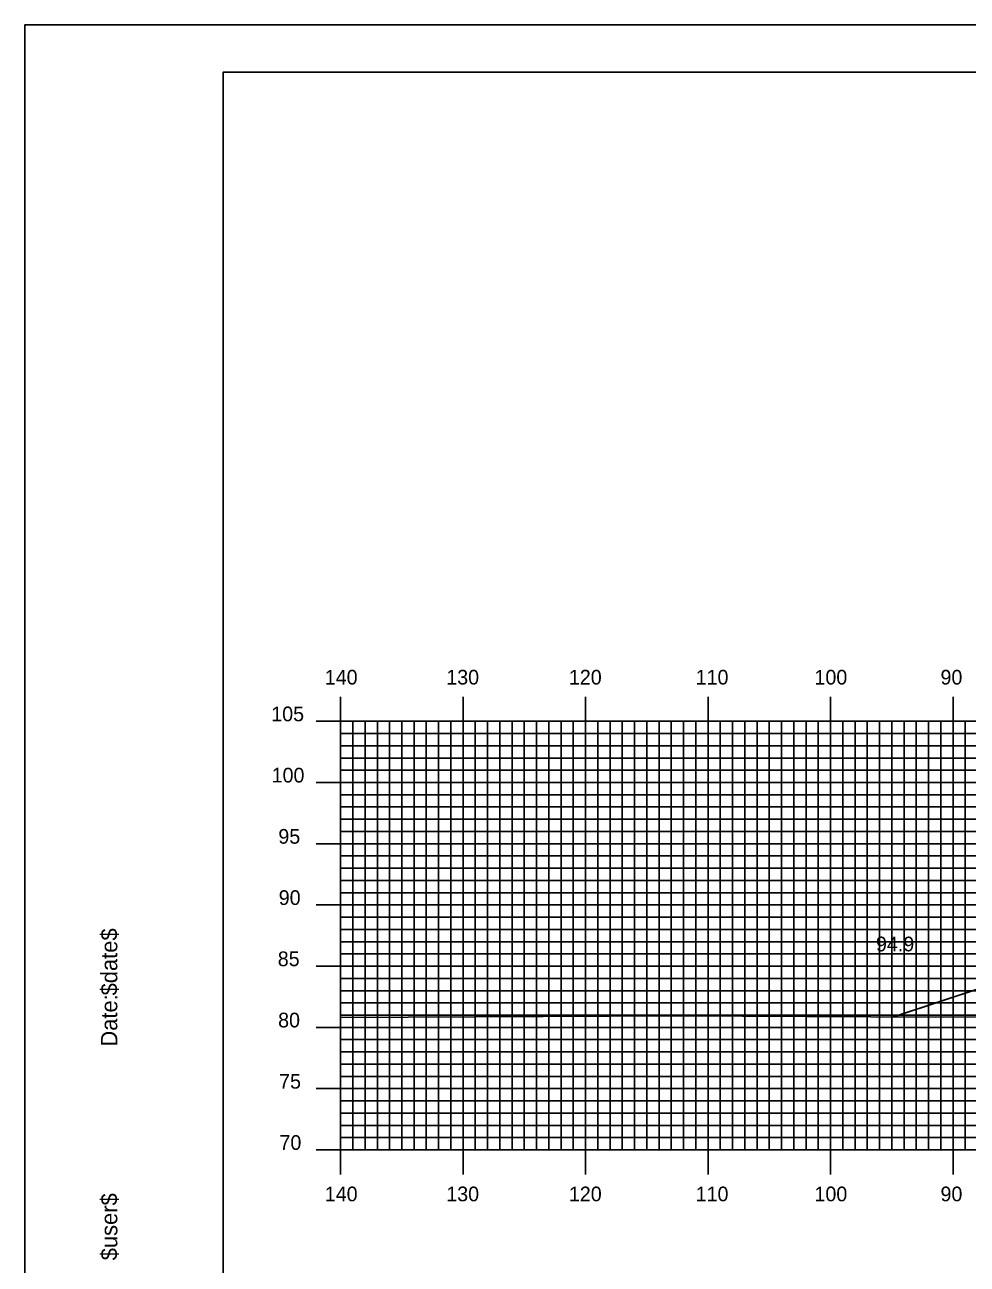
# Model space of a CAD drawing. Extents: x 1756675 to 1757019, y 442591 to 442811.
# Drawn here: x 1756675.3 to 1756752.2, y 442709.3 to 442810.5 of the extents above; entities that cross this region are included whole.
import ezdxf

# ---------------------------------------------------------------- set-up
doc = ezdxf.new("R2010")
doc.units = 0
for name, color, linetype in [('BORDER', 7, 'Continuous'), ('D_Roadway_Centerline', 7, 'Continuous'), ('D_Roadway_SlopeLines', 7, 'Continuous'), ('D_Text_Standard', 7, 'Continuous'), ('H_V ANNOTATION', 7, 'Continuous'), ('MAJOR', 7, 'Continuous'), ('MINOR', 7, 'Continuous'), ('PLOT BOUNDARY', 7, 'Continuous'), ('S_Roadway_Centerline', 7, 'Continuous')]:
    doc.layers.add(name, color=color, linetype=linetype)

msp = doc.modelspace()

# ---------------------------------------------------------------- linework, layer by layer
at = {"layer": 'BORDER'}
msp.add_lwpolyline([(1756691.48, 442596.67), (1757011.48, 442596.67), (1757011.48, 442806.67), (1756691.48, 442806.67)], close=True, dxfattribs=at)
at = {"layer": 'D_Roadway_Centerline'}
msp.add_lwpolyline([(1756746.21, 442729.53), (1756746.45, 442729.6), (1756746.5, 442729.61), (1756784.93, 442742.34), (1756786.99, 442742.43), (1756787.74, 442742.47), (1756787.94, 442742.47), (1756792.2, 442742.67), (1756795.97, 442742.83), (1756797.16, 442742.89), (1756798.1, 442742.93), (1756798.44, 442742.94), (1756798.51, 442742.95), (1756803.7, 442743.18), (1756810.03, 442743.46), (1756829.08, 442743.84), (1756841.08, 442744.08), (1756853.08, 442743.84), (1756862.37, 442743.47), (1756867.31, 442742.24)], dxfattribs=at)
at = {"layer": 'D_Roadway_SlopeLines'}
msp.add_lwpolyline([(1756784.93, 442742.34), (1756746.21, 442729.53)], dxfattribs=at)
at = {"layer": 'MAJOR'}
for p, q in [((1756701.08, 442755.67), (1756701.08, 442753.67)), ((1756711.08, 442755.67), (1756711.08, 442753.67)), ((1756721.08, 442755.67), (1756721.08, 442753.67)), ((1756731.08, 442755.67), (1756731.08, 442753.67)), ((1756741.08, 442755.67), (1756741.08, 442753.67)), ((1756751.08, 442755.67), (1756751.08, 442753.67)), ((1756699.08, 442753.67), (1756701.08, 442753.67)), ((1756701.08, 442753.67), (1756981.08, 442753.67)), ((1756701.08, 442718.67), (1756701.08, 442753.67)), ((1756701.08, 442718.67), (1756701.08, 442753.67)), ((1756701.08, 442753.67), (1756981.08, 442753.67)), ((1756711.08, 442718.67), (1756711.08, 442753.67)), ((1756721.08, 442718.67), (1756721.08, 442753.67)), ((1756731.08, 442718.67), (1756731.08, 442753.67)), ((1756741.08, 442718.67), (1756741.08, 442753.67)), ((1756751.08, 442718.67), (1756751.08, 442753.67)), ((1756699.08, 442748.67), (1756701.08, 442748.67)), ((1756701.08, 442748.67), (1756981.08, 442748.67)), ((1756699.08, 442743.67), (1756701.08, 442743.67)), ((1756701.08, 442743.67), (1756981.08, 442743.67)), ((1756699.08, 442738.67), (1756701.08, 442738.67)), ((1756701.08, 442738.67), (1756981.08, 442738.67)), ((1756699.08, 442733.67), (1756701.08, 442733.67)), ((1756701.08, 442733.67), (1756981.08, 442733.67)), ((1756699.08, 442728.67), (1756701.08, 442728.67)), ((1756701.08, 442728.67), (1756981.08, 442728.67)), ((1756699.08, 442723.67), (1756701.08, 442723.67)), ((1756701.08, 442723.67), (1756981.08, 442723.67)), ((1756699.08, 442718.67), (1756701.08, 442718.67)), ((1756701.08, 442718.67), (1756981.08, 442718.67)), ((1756701.08, 442718.67), (1756981.08, 442718.67)), ((1756701.08, 442716.66), (1756701.08, 442718.67)), ((1756711.08, 442716.66), (1756711.08, 442718.67)), ((1756721.08, 442716.66), (1756721.08, 442718.67)), ((1756731.08, 442716.66), (1756731.08, 442718.67)), ((1756741.08, 442716.66), (1756741.08, 442718.67)), ((1756751.08, 442716.66), (1756751.08, 442718.67))]:
    msp.add_line(p, q, dxfattribs=at)
at = {"layer": 'MINOR'}
for p, q in [((1756702.08, 442718.67), (1756702.08, 442753.67)), ((1756703.08, 442718.67), (1756703.08, 442753.67)), ((1756704.08, 442718.67), (1756704.08, 442753.67)), ((1756705.08, 442718.67), (1756705.08, 442753.67)), ((1756706.08, 442718.67), (1756706.08, 442753.67)), ((1756707.08, 442718.67), (1756707.08, 442753.67)), ((1756708.08, 442718.67), (1756708.08, 442753.67)), ((1756709.08, 442718.67), (1756709.08, 442753.67)), ((1756710.08, 442718.67), (1756710.08, 442753.67)), ((1756712.08, 442718.67), (1756712.08, 442753.67)), ((1756713.08, 442718.67), (1756713.08, 442753.67)), ((1756714.08, 442718.67), (1756714.08, 442753.67)), ((1756715.08, 442718.67), (1756715.08, 442753.67)), ((1756716.08, 442718.67), (1756716.08, 442753.67)), ((1756717.08, 442718.67), (1756717.08, 442753.67)), ((1756718.08, 442718.67), (1756718.08, 442753.67)), ((1756719.08, 442718.67), (1756719.08, 442753.67)), ((1756720.08, 442718.67), (1756720.08, 442753.67)), ((1756722.08, 442718.67), (1756722.08, 442753.67)), ((1756723.08, 442718.67), (1756723.08, 442753.67)), ((1756724.08, 442718.67), (1756724.08, 442753.67)), ((1756725.08, 442718.67), (1756725.08, 442753.67)), ((1756726.08, 442718.67), (1756726.08, 442753.67)), ((1756727.08, 442718.67), (1756727.08, 442753.67)), ((1756728.08, 442718.67), (1756728.08, 442753.67)), ((1756729.08, 442718.67), (1756729.08, 442753.67)), ((1756730.08, 442718.67), (1756730.08, 442753.67)), ((1756732.08, 442718.67), (1756732.08, 442753.67)), ((1756733.08, 442718.67), (1756733.08, 442753.67)), ((1756734.08, 442718.67), (1756734.08, 442753.67)), ((1756735.08, 442718.67), (1756735.08, 442753.67)), ((1756736.08, 442718.67), (1756736.08, 442753.67)), ((1756737.08, 442718.67), (1756737.08, 442753.67)), ((1756738.08, 442718.67), (1756738.08, 442753.67)), ((1756739.08, 442718.67), (1756739.08, 442753.67)), ((1756740.08, 442718.67), (1756740.08, 442753.67)), ((1756742.08, 442718.67), (1756742.08, 442753.67)), ((1756743.08, 442718.67), (1756743.08, 442753.67)), ((1756744.08, 442718.67), (1756744.08, 442753.67)), ((1756745.08, 442718.67), (1756745.08, 442753.67)), ((1756746.08, 442718.67), (1756746.08, 442753.67)), ((1756747.08, 442718.67), (1756747.08, 442753.67)), ((1756748.08, 442718.67), (1756748.08, 442753.67)), ((1756749.08, 442718.67), (1756749.08, 442753.67)), ((1756750.08, 442718.67), (1756750.08, 442753.67)), ((1756752.08, 442718.67), (1756752.08, 442753.67)), ((1756701.08, 442752.67), (1756981.08, 442752.67)), ((1756701.08, 442752.67), (1756703.09, 442752.67)), ((1756701.08, 442751.67), (1756981.08, 442751.67)), ((1756701.08, 442751.67), (1756703.09, 442751.67)), ((1756701.08, 442750.67), (1756981.08, 442750.67)), ((1756701.08, 442750.67), (1756703.09, 442750.67)), ((1756701.08, 442749.67), (1756981.08, 442749.67)), ((1756701.08, 442749.67), (1756703.09, 442749.67)), ((1756701.08, 442747.67), (1756981.08, 442747.67)), ((1756701.08, 442747.67), (1756703.09, 442747.67)), ((1756701.08, 442746.67), (1756981.08, 442746.67)), ((1756701.08, 442746.67), (1756703.09, 442746.67)), ((1756701.08, 442745.67), (1756981.08, 442745.67)), ((1756701.08, 442745.67), (1756703.09, 442745.67)), ((1756701.08, 442744.67), (1756981.08, 442744.67)), ((1756701.08, 442744.67), (1756703.09, 442744.67)), ((1756701.08, 442742.67), (1756981.08, 442742.67)), ((1756701.08, 442742.67), (1756703.09, 442742.67)), ((1756701.08, 442741.67), (1756981.08, 442741.67)), ((1756701.08, 442741.67), (1756703.09, 442741.67)), ((1756701.08, 442740.67), (1756981.08, 442740.67)), ((1756701.08, 442740.67), (1756703.09, 442740.67)), ((1756701.08, 442739.67), (1756981.08, 442739.67)), ((1756701.08, 442739.67), (1756703.09, 442739.67)), ((1756701.08, 442737.67), (1756981.08, 442737.67)), ((1756701.08, 442737.67), (1756703.09, 442737.67)), ((1756701.08, 442736.67), (1756981.08, 442736.67)), ((1756701.08, 442736.67), (1756703.09, 442736.67)), ((1756701.08, 442735.67), (1756981.08, 442735.67)), ((1756701.08, 442735.67), (1756703.09, 442735.67)), ((1756701.08, 442734.67), (1756981.08, 442734.67)), ((1756701.08, 442734.67), (1756703.09, 442734.67)), ((1756701.08, 442732.67), (1756981.08, 442732.67)), ((1756701.08, 442732.67), (1756703.09, 442732.67)), ((1756701.08, 442731.67), (1756981.08, 442731.67)), ((1756701.08, 442731.67), (1756703.09, 442731.67)), ((1756701.08, 442730.67), (1756981.08, 442730.67)), ((1756701.08, 442730.67), (1756703.09, 442730.67)), ((1756701.08, 442729.67), (1756981.08, 442729.67)), ((1756701.08, 442729.67), (1756703.09, 442729.67)), ((1756701.08, 442727.67), (1756981.08, 442727.67)), ((1756701.08, 442727.67), (1756703.09, 442727.67)), ((1756701.08, 442726.67), (1756981.08, 442726.67)), ((1756701.08, 442726.67), (1756703.09, 442726.67)), ((1756701.08, 442725.67), (1756981.08, 442725.67)), ((1756701.08, 442725.67), (1756703.09, 442725.67)), ((1756701.08, 442724.67), (1756981.08, 442724.67)), ((1756701.08, 442724.67), (1756703.09, 442724.67)), ((1756701.08, 442722.67), (1756981.08, 442722.67)), ((1756701.08, 442722.67), (1756703.09, 442722.67)), ((1756701.08, 442721.67), (1756981.08, 442721.67)), ((1756701.08, 442721.67), (1756703.09, 442721.67)), ((1756701.08, 442720.67), (1756981.08, 442720.67)), ((1756701.08, 442720.67), (1756703.09, 442720.67)), ((1756701.08, 442719.67), (1756981.08, 442719.67)), ((1756701.08, 442719.67), (1756703.09, 442719.67))]:
    msp.add_line(p, q, dxfattribs=at)
at = {"layer": 'PLOT BOUNDARY'}
msp.add_lwpolyline([(1756675.3, 442590.55), (1757015.3, 442590.55), (1757015.3, 442810.55), (1756675.3, 442810.55)], close=True, dxfattribs=at)
at = {"layer": 'S_Roadway_Centerline'}
msp.add_lwpolyline([(1756701.08, 442729.47), (1756728.63, 442729.61), (1756749.63, 442729.51), (1756753.73, 442729.53), (1756758.51, 442729.63), (1756775.1, 442729.71), (1756800.77, 442729.86), (1756805.16, 442729.75), (1756821.92, 442729.09), (1756848.37, 442728.26), (1756855.36, 442728.14), (1756864.2, 442727.97), (1756889.97, 442728.34), (1756908.46, 442728.73), (1756912.95, 442728.86), (1756917.38, 442728.94), (1756917.49, 442728.92), (1756956.52, 442729.49), (1756976.5, 442729.7), (1756981.08, 442729.72)], dxfattribs=at)

# ---------------------------------------------------------------- texts
at = {"layer": 'BORDER'}
for s, p in [('$date$', (1756682.85, 442731.28)), ('$date$', (1756682.85, 442731.28)), ('Date:', (1756682.85, 442727.1)), ('Date:', (1756682.85, 442727.1)), ('$user$', (1756682.85, 442709.65)), ('$user$', (1756682.85, 442709.65))]:
    msp.add_text(s, height=1.339, rotation=90, dxfattribs=at).set_placement(p)
at = {"layer": 'D_Text_Standard'}
msp.add_text("94.9'", height=1.2, dxfattribs=at).set_placement((1756744.79, 442734.88))
at = {"layer": 'H_V ANNOTATION'}
for s, p in [('140', (1756699.79, 442756.67)), ('130', (1756709.71, 442756.67)), ('120', (1756719.72, 442756.67)), ('110', (1756730.07, 442756.67)), ('100', (1756739.77, 442756.67)), ('90', (1756750.06, 442756.67)), ('105', (1756695.42, 442753.67)), ('100', (1756695.45, 442748.67)), ('95', (1756696, 442743.67)), ('90', (1756696.03, 442738.67)), ('85', (1756695.95, 442733.67)), ('80', (1756695.98, 442728.67)), ('75', (1756696.06, 442723.67)), ('70', (1756696.09, 442718.67)), ('140', (1756699.79, 442714.47)), ('130', (1756709.71, 442714.47)), ('120', (1756719.72, 442714.47)), ('110', (1756730.07, 442714.47)), ('100', (1756739.77, 442714.47)), ('90', (1756750.06, 442714.47))]:
    msp.add_text(s, height=1.2, dxfattribs=at).set_placement(p)
at = {"layer": 'MAJOR'}
msp.add_text('-', height=0.012, dxfattribs=at).set_placement((1756701.07, 442718.67))

doc.saveas('drawing.dxf')
